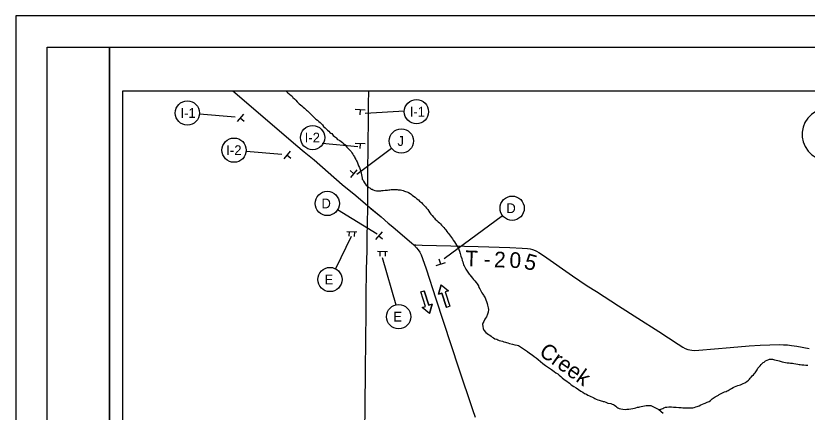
# Model space of a CAD drawing. Extents: x 1 to 1971, y -2 to 1107.
# Drawn here: x 1651.46 to 1664.12, y 1100.26 to 1106.6 of the extents above; entities that cross this region are included whole.
import ezdxf

# ---------------------------------------------------------------- set-up
doc = ezdxf.new("R2010")
doc.units = 0
for name, color, linetype in [('GM_X_County_Road', 7, 'Continuous'), ('GM_X_Minor_River', 7, 'Continuous'), ('GM_X_Minor_River_Text', 7, 'Continuous'), ('GM_X_State_Route', 7, 'Continuous'), ('GM_X_Township_Road', 7, 'Continuous'), ('GM_X_Township_Road_Text', 7, 'Continuous'), ('SH_Border', 7, 'Continuous'), ('SH_Cut_Line', 7, 'Continuous'), ('SH_Data', 7, 'Continuous'), ('SH_Text', 7, 'Continuous'), ('SN_P_Signs', 7, 'Continuous')]:
    doc.layers.add(name, color=color, linetype=linetype)

msp = doc.modelspace()

# ---------------------------------------------------------------- linework, layer by layer
at = {"layer": 'GM_X_County_Road'}
for points in [[(1657.094, 1103.565), (1657.094, 1103.852), (1657.096, 1104.093), (1657.105, 1104.967), (1657.106, 1105.186), (1657.11, 1105.401)], [(1657.094, 1103.565), (1657.094, 1103.852), (1657.096, 1104.093), (1657.105, 1104.967), (1657.106, 1105.186), (1657.11, 1105.401)], [(1657.041, 1099.611), (1657.053, 1100.333), (1657.059, 1100.946), (1657.065, 1101.865), (1657.068, 1102.106), (1657.074, 1102.544), (1657.083, 1102.85), (1657.086, 1103.025), (1657.089, 1103.332), (1657.093, 1103.484), (1657.094, 1103.565)], [(1657.041, 1099.611), (1657.053, 1100.333), (1657.059, 1100.946), (1657.065, 1101.865), (1657.068, 1102.106), (1657.074, 1102.544), (1657.083, 1102.85), (1657.086, 1103.025), (1657.089, 1103.332), (1657.093, 1103.484), (1657.094, 1103.565)]]:
    msp.add_lwpolyline(points, dxfattribs=at)
at = {"layer": 'GM_X_Minor_River'}
for points in [[(1655.784, 1105.401), (1655.812, 1105.371), (1655.842, 1105.347), (1655.866, 1105.328), (1655.882, 1105.314), (1655.897, 1105.295), (1655.919, 1105.276), (1655.94, 1105.255), (1655.964, 1105.225)], [(1655.964, 1105.225), (1655.996, 1105.195), (1656.041, 1105.16), (1656.062, 1105.14), (1656.081, 1105.124), (1656.099, 1105.108), (1656.112, 1105.094), (1656.128, 1105.081), (1656.144, 1105.064), (1656.16, 1105.048), (1656.216, 1104.999), (1656.229, 1104.98), (1656.248, 1104.967), (1656.264, 1104.95), (1656.288, 1104.931), (1656.312, 1104.912), (1656.33, 1104.893), (1656.349, 1104.877), (1656.367, 1104.858), (1656.386, 1104.834), (1656.41, 1104.809), (1656.431, 1104.79), (1656.449, 1104.774), (1656.471, 1104.755), (1656.489, 1104.738), (1656.503, 1104.725), (1656.516, 1104.717), (1656.529, 1104.706), (1656.542, 1104.69), (1656.561, 1104.671), (1656.577, 1104.662), (1656.59, 1104.649), (1656.611, 1104.624), (1656.635, 1104.613), (1656.649, 1104.605), (1656.67, 1104.589), (1656.689, 1104.575), (1656.707, 1104.559), (1656.731, 1104.537), (1656.755, 1104.507), (1656.784, 1104.475), (1656.811, 1104.45), (1656.826, 1104.431), (1656.84, 1104.41), (1656.853, 1104.391), (1656.866, 1104.367), (1656.879, 1104.348), (1656.887, 1104.329), (1656.9, 1104.304), (1656.913, 1104.283), (1656.921, 1104.264), (1656.934, 1104.237), (1656.947, 1104.205), (1656.96, 1104.178), (1656.971, 1104.143), (1656.981, 1104.113), (1656.986, 1104.086), (1656.996, 1104.03), (1657.001, 1104.008), (1657.006, 1103.987), (1657.017, 1103.971), (1657.027, 1103.955), (1657.043, 1103.93), (1657.054, 1103.917), (1657.067, 1103.895), (1657.093, 1103.871), (1657.112, 1103.857), (1657.125, 1103.849), (1657.147, 1103.832), (1657.163, 1103.827), (1657.181, 1103.819), (1657.205, 1103.81), (1657.232, 1103.805), (1657.254, 1103.802), (1657.272, 1103.801), (1657.286, 1103.804), (1657.302, 1103.804), (1657.318, 1103.806), (1657.342, 1103.808), (1657.369, 1103.813), (1657.393, 1103.813), (1657.407, 1103.816), (1657.431, 1103.818), (1657.445, 1103.821), (1657.466, 1103.823), (1657.488, 1103.823), (1657.504, 1103.822), (1657.525, 1103.825), (1657.547, 1103.825), (1657.563, 1103.824), (1657.582, 1103.821), (1657.603, 1103.821), (1657.619, 1103.818), (1657.659, 1103.807), (1657.681, 1103.799), (1657.699, 1103.793), (1657.718, 1103.785), (1657.734, 1103.779), (1657.747, 1103.774), (1657.769, 1103.76), (1657.785, 1103.749)], [(1657.785, 1103.749), (1657.806, 1103.735), (1657.827, 1103.719), (1657.851, 1103.7), (1657.878, 1103.676), (1657.904, 1103.659), (1657.923, 1103.64), (1657.939, 1103.629), (1657.952, 1103.616), (1657.971, 1103.594), (1657.995, 1103.57), (1658.016, 1103.545), (1658.034, 1103.524), (1658.053, 1103.502), (1658.071, 1103.477), (1658.087, 1103.453), (1658.103, 1103.432), (1658.121, 1103.407), (1658.143, 1103.383), (1658.159, 1103.367), (1658.174, 1103.348), (1658.196, 1103.326), (1658.22, 1103.307), (1658.241, 1103.29), (1658.257, 1103.274), (1658.273, 1103.255), (1658.288, 1103.236), (1658.31, 1103.215), (1658.326, 1103.196), (1658.341, 1103.177), (1658.357, 1103.155), (1658.376, 1103.133), (1658.389, 1103.117), (1658.4, 1103.101), (1658.415, 1103.079), (1658.431, 1103.058), (1658.447, 1103.036), (1658.46, 1103.014), (1658.481, 1102.987), (1658.494, 1102.96), (1658.51, 1102.936), (1658.542, 1102.879), (1658.552, 1102.863), (1658.56, 1102.836), (1658.57, 1102.801), (1658.583, 1102.758), (1658.596, 1102.721), (1658.604, 1102.691), (1658.612, 1102.667), (1658.619, 1102.64), (1658.627, 1102.621), (1658.635, 1102.605), (1658.643, 1102.591), (1658.651, 1102.57), (1658.661, 1102.551), (1658.672, 1102.535), (1658.685, 1102.519), (1658.696, 1102.502), (1658.703, 1102.489), (1658.717, 1102.473), (1658.727, 1102.459), (1658.748, 1102.432), (1658.767, 1102.408), (1658.785, 1102.386), (1658.807, 1102.362), (1658.825, 1102.34), (1658.841, 1102.318), (1658.854, 1102.299), (1658.865, 1102.283), (1658.872, 1102.259), (1658.888, 1102.235), (1658.901, 1102.205), (1658.92, 1102.173), (1658.935, 1102.151), (1658.946, 1102.137), (1658.951, 1102.124), (1658.959, 1102.108), (1658.97, 1102.092), (1658.975, 1102.078), (1658.983, 1102.059), (1658.99, 1102.035), (1659.003, 1102.003), (1659.011, 1101.976), (1659.016, 1101.952), (1659.021, 1101.933), (1659.026, 1101.906), (1659.018, 1101.861), (1659.007, 1101.829), (1658.995, 1101.791), (1658.976, 1101.765), (1658.965, 1101.751), (1658.949, 1101.714), (1658.935, 1101.688), (1658.929, 1101.672), (1658.934, 1101.634), (1658.939, 1101.604), (1658.952, 1101.577), (1658.984, 1101.537), (1659.024, 1101.504), (1659.045, 1101.496), (1659.067, 1101.477)], [(1659.067, 1101.477), (1659.083, 1101.466), (1659.104, 1101.455), (1659.125, 1101.439), (1659.157, 1101.43), (1659.176, 1101.419), (1659.195, 1101.411), (1659.248, 1101.397), (1659.27, 1101.391), (1659.294, 1101.385), (1659.312, 1101.38), (1659.334, 1101.372), (1659.363, 1101.363), (1659.409, 1101.352), (1659.444, 1101.343), (1659.484, 1101.335), (1659.505, 1101.332), (1659.521, 1101.318), (1659.55, 1101.299), (1659.582, 1101.277), (1659.614, 1101.258), (1659.646, 1101.236), (1659.678, 1101.206), (1659.724, 1101.179), (1659.755, 1101.157), (1659.785, 1101.133), (1659.817, 1101.105), (1659.857, 1101.075), (1659.896, 1101.045), (1659.939, 1101.013), (1659.984, 1100.977), (1660.035, 1100.945), (1660.075, 1100.917), (1660.104, 1100.895), (1660.133, 1100.879), (1660.157, 1100.855), (1660.181, 1100.835), (1660.205, 1100.811), (1660.234, 1100.789), (1660.264, 1100.77), (1660.285, 1100.756), (1660.298, 1100.746), (1660.319, 1100.729), (1660.349, 1100.699), (1660.391, 1100.677), (1660.426, 1100.653), (1660.463, 1100.626), (1660.5, 1100.601), (1660.535, 1100.582), (1660.562, 1100.563), (1660.591, 1100.552), (1660.615, 1100.538), (1660.639, 1100.527), (1660.711, 1100.494), (1660.725, 1100.485), (1660.749, 1100.474), (1660.775, 1100.463), (1660.797, 1100.458), (1660.81, 1100.452), (1660.829, 1100.444), (1660.848, 1100.438), (1660.861, 1100.435), (1660.877, 1100.433), (1660.901, 1100.424), (1660.933, 1100.41), (1660.979, 1100.402), (1661.005, 1100.391), (1661.024, 1100.385), (1661.04, 1100.374), (1661.059, 1100.358), (1661.08, 1100.344), (1661.096, 1100.336), (1661.115, 1100.325), (1661.139, 1100.317), (1661.174, 1100.311), (1661.214, 1100.308), (1661.238, 1100.31), (1661.254, 1100.31), (1661.27, 1100.312), (1661.3, 1100.32), (1661.332, 1100.325), (1661.359, 1100.33), (1661.383, 1100.335), (1661.41, 1100.343), (1661.429, 1100.345), (1661.443, 1100.35), (1661.467, 1100.355), (1661.496, 1100.36), (1661.518, 1100.365), (1661.545, 1100.37), (1661.572, 1100.373), (1661.591, 1100.372), (1661.609, 1100.372), (1661.623, 1100.369), (1661.641, 1100.361), (1661.674, 1100.347), (1661.698, 1100.333), (1661.716, 1100.322), (1661.73, 1100.317), (1661.748, 1100.309), (1661.762, 1100.308)], [(1661.762, 1100.308), (1661.783, 1100.314), (1661.797, 1100.316), (1661.813, 1100.324), (1661.832, 1100.332), (1661.856, 1100.342), (1661.878, 1100.347), (1661.907, 1100.352), (1661.934, 1100.352), (1661.953, 1100.352), (1661.982, 1100.346), (1662.025, 1100.343), (1662.071, 1100.339), (1662.106, 1100.339), (1662.135, 1100.336), (1662.165, 1100.335), (1662.192, 1100.332), (1662.218, 1100.332), (1662.243, 1100.332), (1662.267, 1100.334), (1662.294, 1100.336), (1662.315, 1100.341), (1662.34, 1100.349), (1662.364, 1100.354), (1662.38, 1100.359), (1662.396, 1100.367), (1662.423, 1100.383), (1662.448, 1100.393), (1662.472, 1100.404), (1662.493, 1100.411), (1662.52, 1100.422), (1662.539, 1100.43), (1662.553, 1100.437), (1662.577, 1100.453), (1662.591, 1100.466), (1662.604, 1100.477), (1662.618, 1100.49), (1662.634, 1100.501), (1662.648, 1100.508), (1662.702, 1100.537), (1662.715, 1100.545), (1662.737, 1100.558), (1662.767, 1100.574), (1662.799, 1100.587), (1662.826, 1100.597), (1662.845, 1100.605), (1662.858, 1100.61), (1662.875, 1100.621), (1662.891, 1100.631), (1662.91, 1100.644), (1662.937, 1100.66), (1662.961, 1100.67), (1662.988, 1100.681), (1663.013, 1100.689), (1663.037, 1100.696), (1663.058, 1100.701), (1663.077, 1100.712), (1663.099, 1100.722), (1663.123, 1100.735), (1663.142, 1100.746), (1663.156, 1100.756), (1663.183, 1100.777), (1663.199, 1100.793), (1663.213, 1100.806), (1663.226, 1100.825), (1663.245, 1100.844), (1663.262, 1100.859), (1663.278, 1100.881), (1663.292, 1100.894), (1663.303, 1100.907), (1663.314, 1100.923), (1663.322, 1100.942), (1663.333, 1100.966), (1663.352, 1100.987), (1663.368, 1101.005), (1663.387, 1101.024), (1663.406, 1101.048), (1663.42, 1101.058), (1663.434, 1101.066), (1663.458, 1101.087), (1663.507, 1101.105), (1663.52, 1101.11), (1663.536, 1101.11), (1663.552, 1101.113), (1663.568, 1101.11), (1663.582, 1101.107), (1663.601, 1101.101), (1663.627, 1101.096), (1663.654, 1101.09), (1663.673, 1101.084), (1663.692, 1101.081), (1663.708, 1101.076), (1663.724, 1101.07), (1663.748, 1101.062), (1663.775, 1101.059), (1663.801, 1101.053), (1663.834, 1101.053), (1663.858, 1101.05), (1663.885, 1101.047), (1663.911, 1101.041), (1663.943, 1101.038)], [(1663.943, 1101.038), (1663.973, 1101.032), (1663.992, 1101.029), (1664.01, 1101.026), (1664.035, 1101.023), (1664.053, 1101.02), (1664.069, 1101.02), (1664.102, 1101.017), (1664.134, 1101.017)], [(1661.748, 1100.309), (1661.82, 1100.251)]]:
    msp.add_lwpolyline(points, dxfattribs=at)
at = {"layer": 'GM_X_State_Route'}
for points in [[(1654.936, 1105.401), (1655.677, 1104.768), (1655.943, 1104.54), (1656.076, 1104.427), (1656.234, 1104.298), (1656.685, 1103.905), (1656.904, 1103.727), (1657.094, 1103.565), (1657.142, 1103.523)], [(1654.936, 1105.401), (1655.677, 1104.768), (1655.943, 1104.54), (1656.076, 1104.427), (1656.234, 1104.298), (1656.685, 1103.905), (1656.904, 1103.727), (1657.094, 1103.565), (1657.142, 1103.523)], [(1657.142, 1103.523), (1657.305, 1103.385), (1657.422, 1103.285), (1657.492, 1103.225), (1657.647, 1103.092), (1657.794, 1102.971), (1657.83, 1102.938), (1657.873, 1102.894), (1657.901, 1102.859), (1657.925, 1102.822), (1657.945, 1102.782), (1657.969, 1102.72), (1658.025, 1102.554), (1658.182, 1102.076), (1658.547, 1100.975), (1658.767, 1100.309), (1658.811, 1100.186)]]:
    msp.add_lwpolyline(points, dxfattribs=at)
at = {"layer": 'GM_X_Township_Road'}
msp.add_lwpolyline([(1657.83, 1102.938), (1657.864, 1102.937), (1657.964, 1102.933), (1658.423, 1102.926), (1658.861, 1102.913), (1659.364, 1102.895), (1659.561, 1102.886), (1659.647, 1102.88), (1659.69, 1102.874), (1659.731, 1102.863), (1659.771, 1102.847), (1659.791, 1102.838), (1659.828, 1102.816), (1659.902, 1102.769), (1660.37, 1102.446), (1660.605, 1102.286), (1660.752, 1102.191), (1661.102, 1101.966), (1661.416, 1101.767), (1661.748, 1101.554), (1662.059, 1101.35), (1662.133, 1101.303), (1662.173, 1101.283), (1662.214, 1101.267), (1662.244, 1101.259), (1662.279, 1101.254), (1662.323, 1101.251), (1662.39, 1101.254), (1662.891, 1101.296), (1663.197, 1101.323), (1663.371, 1101.336), (1663.524, 1101.343), (1663.677, 1101.345), (1663.742, 1101.343), (1663.807, 1101.339), (1663.872, 1101.331), (1663.958, 1101.317), (1664.152, 1101.281)], dxfattribs=at)
msp.add_lwpolyline([(1657.83, 1102.938), (1657.864, 1102.937), (1657.964, 1102.933), (1658.423, 1102.926), (1658.861, 1102.913), (1659.364, 1102.895), (1659.561, 1102.886), (1659.647, 1102.88), (1659.69, 1102.874), (1659.731, 1102.863), (1659.771, 1102.847), (1659.791, 1102.838), (1659.828, 1102.816), (1659.902, 1102.769), (1660.37, 1102.446), (1660.605, 1102.286), (1660.752, 1102.191), (1661.102, 1101.966), (1661.416, 1101.767), (1661.748, 1101.554), (1662.059, 1101.35), (1662.133, 1101.303), (1662.173, 1101.283), (1662.214, 1101.267), (1662.244, 1101.259), (1662.279, 1101.254), (1662.323, 1101.251), (1662.39, 1101.254), (1662.891, 1101.296), (1663.197, 1101.323), (1663.371, 1101.336), (1663.524, 1101.343), (1663.677, 1101.345), (1663.742, 1101.343), (1663.807, 1101.339), (1663.872, 1101.331), (1663.958, 1101.317), (1664.152, 1101.281)], dxfattribs=at)
at = {"layer": 'SH_Border'}
for points in [[(1651.963, 1106.101), (1652.963, 1106.101), (1652.963, 1085.101), (1651.963, 1085.101)], [(1652.963, 1106.101), (1684.963, 1106.101), (1684.963, 1085.101), (1652.963, 1085.101)]]:
    msp.add_lwpolyline(points, close=True, dxfattribs=at)
at = {"layer": 'SH_Cut_Line'}
msp.add_lwpolyline([(1651.463, 1084.601), (1685.463, 1084.601), (1685.463, 1106.601), (1651.463, 1106.601)], close=True, dxfattribs=at)
at = {"layer": 'SH_Data'}
msp.add_lwpolyline([(1653.176, 1105.401), (1672.202, 1105.401), (1672.202, 1085.801), (1653.176, 1085.801)], close=True, dxfattribs=at)
msp.add_arc((1664.456, 1104.705), 0.415, 129.7798, 129.7633, dxfattribs=at)
at = {"layer": 'SH_Text'}
for p, q in [((1654.972, 1104.978), (1654.401, 1105.028)), ((1657.049, 1105.045), (1657.679, 1105.081)), ((1656.935, 1104.508), (1656.365, 1104.557)), ((1655.719, 1104.384), (1655.148, 1104.434)), ((1656.916, 1104.072), (1657.474, 1104.486)), ((1657.242, 1103.11), (1656.61, 1103.499)), ((1658.314, 1102.72), (1659.247, 1103.41)), ((1656.829, 1103.072), (1656.576, 1102.558)), ((1657.322, 1102.737), (1657.54, 1101.979)), ((1658.265, 1102.3), (1658.224, 1102.152)), ((1658.265, 1102.3), (1658.385, 1102.205)), ((1657.942, 1102.186), (1657.997, 1102.204)), ((1658.017, 1101.956), (1657.942, 1102.186)), ((1658.072, 1101.973), (1657.997, 1102.204)), ((1658.224, 1102.152), (1658.276, 1102.169)), ((1658.276, 1102.169), (1658.351, 1101.939)), ((1658.385, 1102.205), (1658.331, 1102.187)), ((1658.331, 1102.187), (1658.406, 1101.957)), ((1658.124, 1101.99), (1658.072, 1101.973)), ((1658.082, 1101.843), (1658.124, 1101.99)), ((1657.962, 1101.938), (1658.017, 1101.956)), ((1658.082, 1101.843), (1657.962, 1101.938)), ((1658.406, 1101.957), (1658.351, 1101.939))]:
    msp.add_line(p, q, dxfattribs=at)
for points in [[(1657.094, 1103.565), (1657.305, 1103.385), (1657.422, 1103.285), (1657.492, 1103.225), (1657.647, 1103.092), (1657.794, 1102.971), (1657.83, 1102.938), (1657.873, 1102.894), (1657.901, 1102.859), (1657.925, 1102.822), (1657.945, 1102.782), (1657.969, 1102.72), (1658.025, 1102.554), (1658.182, 1102.076), (1658.547, 1100.975), (1658.767, 1100.309), (1658.811, 1100.186)], [(1657.142, 1103.523), (1657.305, 1103.385), (1657.422, 1103.285), (1657.492, 1103.225), (1657.647, 1103.092), (1657.794, 1102.971), (1657.83, 1102.938), (1657.873, 1102.894), (1657.901, 1102.859), (1657.925, 1102.822), (1657.945, 1102.782), (1657.969, 1102.72), (1658.025, 1102.554), (1658.182, 1102.076), (1658.547, 1100.975), (1658.767, 1100.309), (1658.811, 1100.186)]]:
    msp.add_lwpolyline(points, dxfattribs=at)
for points in [[(1658.351, 1101.939), (1658.276, 1102.169), (1658.224, 1102.152), (1658.265, 1102.3), (1658.385, 1102.205), (1658.331, 1102.187), (1658.406, 1101.957)], [(1657.997, 1102.204), (1658.072, 1101.973), (1658.124, 1101.99), (1658.082, 1101.843), (1657.962, 1101.938), (1658.017, 1101.956), (1657.942, 1102.186)]]:
    msp.add_lwpolyline(points, close=True, dxfattribs=at)
for centre in [(1654.208, 1105.047), (1657.872, 1105.068), (1656.21, 1104.654), (1657.63, 1104.6), (1654.955, 1104.453), (1656.445, 1103.601), (1659.403, 1103.525), (1656.488, 1102.385), (1657.587, 1101.791)]:
    msp.add_circle(centre, 0.194, dxfattribs=at)
at = {"layer": 'SN_P_Signs'}
for p, q in [((1655.106, 1105.031), (1655.002, 1104.91)), ((1657.049, 1105.093), (1656.889, 1105.102)), ((1656.969, 1105.097), (1656.965, 1105.018)), ((1655.054, 1104.97), (1655.115, 1104.918)), ((1657.049, 1104.553), (1656.889, 1104.562)), ((1656.969, 1104.557), (1656.965, 1104.478)), ((1655.853, 1104.437), (1655.749, 1104.315)), ((1655.801, 1104.376), (1655.862, 1104.324)), ((1656.821, 1104.014), (1656.924, 1104.136)), ((1656.872, 1104.075), (1656.811, 1104.126)), ((1656.757, 1103.153), (1656.917, 1103.148)), ((1656.794, 1103.152), (1656.792, 1103.077)), ((1656.879, 1103.149), (1656.876, 1103.074)), ((1657.322, 1103.146), (1657.218, 1103.024)), ((1657.27, 1103.085), (1657.331, 1103.033)), ((1657.251, 1102.838), (1657.411, 1102.833)), ((1657.288, 1102.837), (1657.286, 1102.761)), ((1657.373, 1102.834), (1657.37, 1102.759)), ((1658.187, 1102.608), (1658.338, 1102.659)), ((1658.263, 1102.633), (1658.237, 1102.709))]:
    msp.add_line(p, q, dxfattribs=at)

# ---------------------------------------------------------------- texts
at = {"layer": 'GM_X_Minor_River_Text'}
msp.add_text('Creek', height=0.25, rotation=324.5413, dxfattribs=at).set_placement((1659.818, 1101.189))
at = {"layer": 'GM_X_Township_Road_Text'}
for s, rotation, p in [('T', 357.758, (1658.646, 1102.601)), ('2', 357.7647, (1659.109, 1102.583)), ('0', 357.7802, (1659.356, 1102.574)), ('5', 344.4049, (1659.578, 1102.568)), ('-', 357.7621, (1658.945, 1102.59))]:
    msp.add_text(s, height=0.25, rotation=rotation, dxfattribs=at).set_placement(p)
at = {"layer": 'SH_Text'}
for s, p in [('I-1', (1657.765, 1104.99)), ('I-1', (1654.097, 1104.969)), ('I-2', (1656.085, 1104.576)), ('J', (1657.568, 1104.522)), ('I-2', (1654.83, 1104.375)), ('D', (1656.352, 1103.523)), ('D', (1659.31, 1103.447)), ('E', (1656.403, 1102.307)), ('E', (1657.502, 1101.713))]:
    msp.add_text(s, height=0.156, dxfattribs=at).set_placement(p)

doc.saveas('drawing.dxf')
